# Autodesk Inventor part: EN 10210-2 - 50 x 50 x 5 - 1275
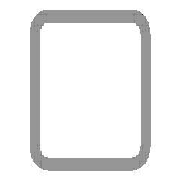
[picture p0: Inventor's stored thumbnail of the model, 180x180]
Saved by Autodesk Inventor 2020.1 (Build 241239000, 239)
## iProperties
_CCFamilyMember: 16
_CCFamilyDisplayName: DIN EN 10210-2 (USAS B17.1 quadratisch) - Rohrleitung — In Klammern angegebene Größen wurden aufgehoben
_FrameMemberDoc: Frame Member File
_Version: 15.0.0
_GetPNFromCC: 1
IsCustomPart: 1
Created: 2019-10
Part Number: EN 10210-2 - 50 x 50 x 5 - 1275
Material: Stahl, weich
Description: Rohrleitung
Document SubType Name: Modeling
Standard: DIN
Designer: lutzd
Standard Revision: 2006-07
Standards Organization: DIN
Language: de-DE
Size Designation: 50 x 50 x 5
Categories: <MemberInstance><Categories><Category DisplayName="Profile" InternalName="089c4875-fa83-4c05-b084-43b9cc11f5ed" Mnemonic="GRDR"><CategoryParameter DisplayName="
Stock Number: 50 x 50 x 5
Mass: 8739.39 g
Surface Area: 4333.85 cm^2
Volume: 1113.3 cm^3
Density: 7.85 g/cm^3
Appearance: Halbpoliert
G_L: 1275,000 mm
G_W: 50,000 mm
G_H: 50,000 mm
Dimensions: 50x50x1275 mm
Mass: 8,739 kg
DocNumber: ADSK-014092
Folder: .
+BD579F37-3FEE-4E25-BD65-AC790D309027+SCHNITTDETAIL1: Schnittwinkel 90,00 grd
+2608A4A2-EBB8-4CA7-8EE6-72A09880D8C3+SCHNITTDETAIL2: Schnittwinkel 90,00 grd
Title: Profil-Bauteil
Author: lutzd
Revision Number: -
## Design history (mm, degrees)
node "Startebene"
node "Endebene"
sketch "Skizze"
  geometry: L1 (-25, -17.5)-(-25, 17.5); L2 (-17.5, 25)-(17.5, 25); L3 (25, 17.5)-(25, -17.5); L4 (17.5, -25)-(-17.5, -25); L5 (-15, 20)-(15, 20); L6 (20, 15)-(20, -15); L7 (15, -20)-(-15, -20); L8 (-20, -15)-(-20, 15); L9 (0, 37.175)-(0, -37.175) reference; L10 (-37.175, 0)-(37.175, 0) reference; A1 r 7.5 centre (-17.5, -17.5) between (-25, -17.5) and (-17.5, -25); A2 r 7.5 centre (-17.5, 17.5) between (-17.5, 25) and (-25, 17.5); A3 r 7.5 centre (17.5, 17.5) between (25, 17.5) and (17.5, 25); A4 r 7.5 centre (17.5, -17.5) between (17.5, -25) and (25, -17.5); A5 r 5 centre (-15, -15) between (-20, -15) and (-15, -20); A6 r 5 centre (-15, 15) between (-15, 20) and (-20, 15); A7 r 5 centre (15, 15) between (20, 15) and (15, 20); A8 r 5 centre (15, -15) between (15, -20) and (20, -15)
  constraints: 16 end point, 16 point on circle, 16 tangent, 8 centre point, 6 equal radius, 4 parallel, 2 perpendicular, 2 other
  dimensions: "d7" = 7.5 radius of A1 (= G_IR); "d10" = 50 distance between parallel lines of L2 L4 (= G_H); "d11" = 50 distance between parallel lines of L1 L3 (= G_W); "d12" = 5 distance between parallel lines of L3 L6 (= G_T); "d15" = 25 distance between parallel lines of L2 L10 (= 0.5 x d10); "d16" = 25 distance between parallel lines of L9 L3 (= 0.5 x d11); "d19" = 5 radius of A5 (= G_T); "d20" = 5 distance between parallel lines of L4 L7 (= G_T)
extrude "Körper" new body sketch "Skizze" stored distance "d3" = 1275 (= G_L); taper "d4" = 0 deg
node "Driven Length"
  sketch "Sketch3"
    geometry: L1 (0, 0)-(10, 0) reference
    constraints: 2 end point, 1 horizontal
  workplane "Work Plane3"
  sketch "Sketch4"
    geometry: L1 (-2, 50)-(12, 50) reference; L2 (-2, 1325)-(12, 1325) reference
    dimensions: "d18" = 1275 distance between parallel lines of L1 L2 (derived)
workplane "Arbeitsebene4"
feature "Trennen1"
workplane "Arbeitsebene5"
feature "Trennen2"
body "Solid1"
other parameters: "G_W" = 50 [user parameter; used in 1 equation term], "G_H" = 50 [user parameter; used in 1 equation term], "G_T" = 5 [user parameter; used in 3 equation terms], "G_IR" = 7.5 [user parameter; used in 1 equation term], "G_L" = 1275 (= d18) [user parameter; used in 1 equation term], "d14" = 1325 (= G_OFFSET_END + B_L), "B_L" = 1375 [user parameter; used in 1 equation term], "d17" = 90 deg
